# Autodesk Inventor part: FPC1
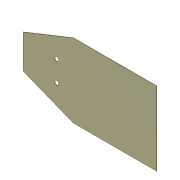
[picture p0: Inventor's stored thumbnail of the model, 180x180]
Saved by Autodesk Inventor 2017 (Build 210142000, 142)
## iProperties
Part Number: FPC1
Material: ポリプロピレン
Document SubType Name: Modeling
Designer: kyushu-hep
Density: 0.899 g/cm^3
Appearance: 滑らか - 灰色
Author: kyushu-hep
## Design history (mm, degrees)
sketch "スケッチ2"
  geometry: L1 (16.961, 8.668)-(16.961, -7.832); L2 (16.961, -7.832)-(-7.639, -17.632); L3 (-7.639, -17.632)-(-48.519, -17.632); L4 (-48.519, -17.632)-(-48.519, 18.468); L5 (-48.519, 18.468)-(-7.639, 18.468); L6 (-7.639, 18.468)-(16.961, 8.668); 1 further point
  constraints: 12 end point, 3 perpendicular, 1 equal length, 1 vertical
  dimensions: "d5" = 16.5 distance of L1.start L1.end; "d6" = 40.88 distance of L2.end L3.end; "d7" = 36.1 distance of L3.end L4.end; "d8" = 40.88 distance of L4.end L5.end; "d9" = 65.48 distance between parallel lines of L1 L4
extrude "押し出し1" new body sketch "スケッチ2" distance "d10" = 0.2; taper "d11" = 0 deg
sketch "スケッチ3"
  geometry: L1 (48.519, -18.468)-(48.519, 17.632) reference; L2 (7.639, -18.468)-(48.519, -18.468) reference; L3 (48.519, 17.632)-(7.639, 17.632) reference; C1 r 1 at (-0.481, -5.468); C2 r 1 at (-0.481, 4.632); 1 further point
  constraints: 2 centre point
  dimensions: "d12" = 2 diameter of C1; "d13" = 2 diameter of C2; "d14" = 49 distance from line of C1.centre L1; "d15" = 13 distance from line of C1.centre L2; "d16" = 13 distance from line of C2.centre L3; "d17" = 49 distance from line of C2.centre L1
extrude "押し出し2" cut sketch "スケッチ3" distance "d18" = 0.2; taper "d19" = 0 deg
node "ソリッド1"
